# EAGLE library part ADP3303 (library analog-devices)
ANALOG DEVICES
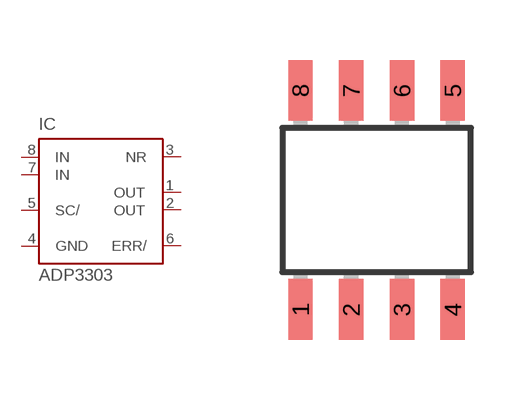
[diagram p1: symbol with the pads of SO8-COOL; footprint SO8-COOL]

Designator prefix IC

## ADP3303 (MPN: ADP3303ARZ-5; OC_FARNELL: 1465451; OC_NEWARK: 19M8716)  [SO8-COOL]
1  OUT  pas
2  OUT  pas
3  NR  pas
4  GND  pwr
5  SC/  in
6  ERR/  oc
7  IN  in
8  IN  in

## Footprint SO8-COOL (pad centres in mm)
SMALL OUTLINE INTEGRATED CIRCUIT
smd 0.61 x 1.524: 1 -1.905,-2.743; 2 -0.635,-2.743; 3 0.635,-2.743; 4 1.905,-2.743; 5 1.905,2.743; 6 0.635,2.743; 7 -0.635,2.743; 8 -1.905,2.743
